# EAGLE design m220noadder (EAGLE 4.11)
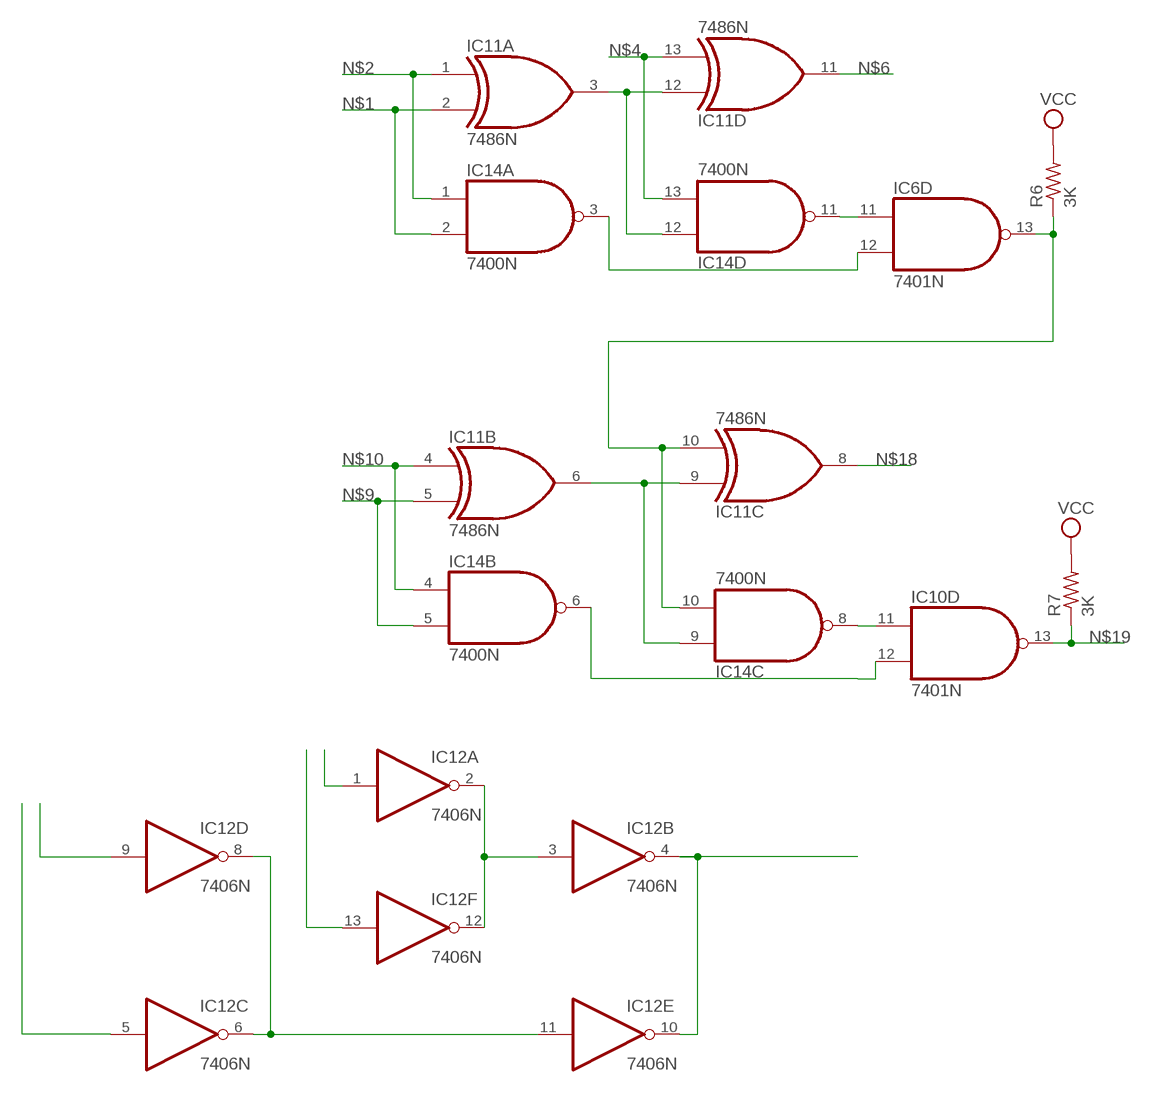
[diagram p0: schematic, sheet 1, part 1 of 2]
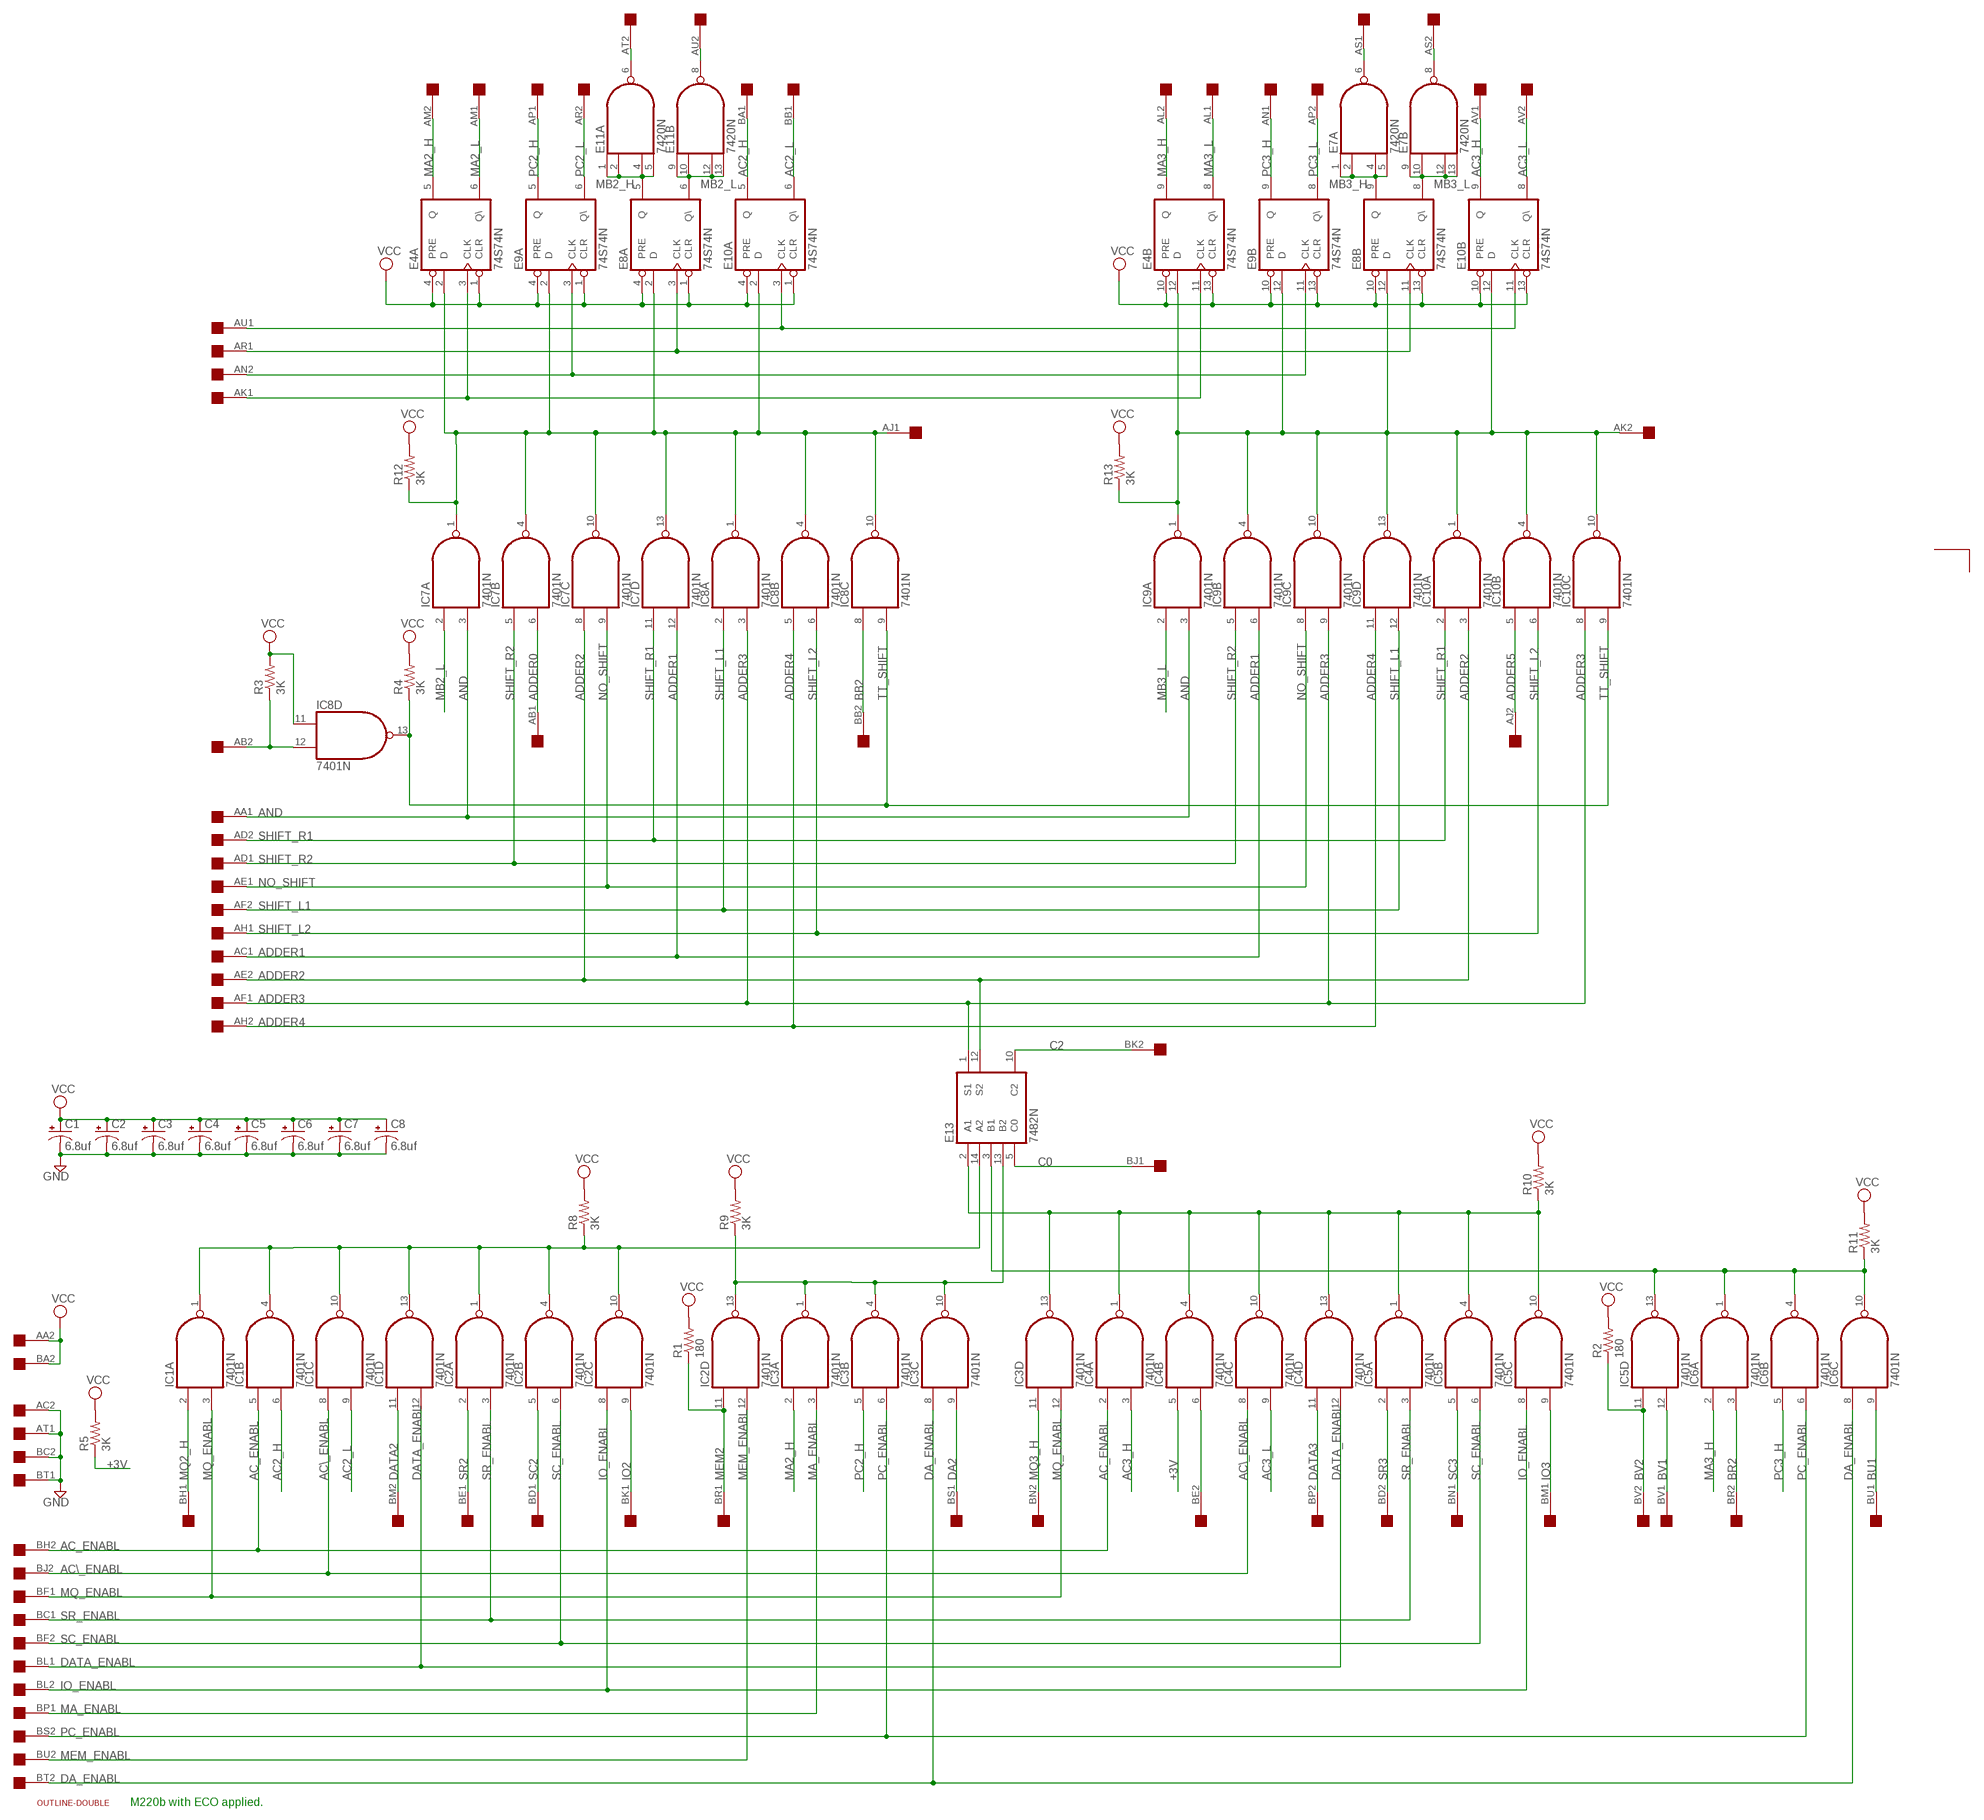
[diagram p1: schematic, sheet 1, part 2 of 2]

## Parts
C1  6.8uf  CPOL-USE15-5AXIAL  [E15-5]
C2  6.8uf  CPOL-USE15-5AXIAL  [E15-5]
C3  6.8uf  CPOL-USE15-5AXIAL  [E15-5]
C4  6.8uf  CPOL-USE15-5AXIAL  [E15-5]
C5  6.8uf  CPOL-USE15-5AXIAL  [E15-5]
C6  6.8uf  CPOL-USE15-5AXIAL  [E15-5]
C7  6.8uf  CPOL-USE15-5AXIAL  [E15-5]
C8  6.8uf  CPOL-USE15-5AXIAL  [E15-5]
E4  74S74N  [DIL14]
E7  7420N  74S20N  [DIL14]
E8  74S74N  [DIL14]
E9  74S74N  [DIL14]
E10  74S74N  [DIL14]
E11  7420N  74S20N  [DIL14]
E13  7482N  [DIL14]
IC1  7401N  [DIL14]
IC2  7401N  [DIL14]
IC3  7401N  [DIL14]
IC4  7401N  [DIL14]
IC5  7401N  [DIL14]
IC6  7401N  [DIL14]
IC7  7401N  [DIL14]
IC8  7401N  [DIL14]
IC9  7401N  [DIL14]
IC10  7401N  [DIL14]
IC11  7486N  [DIL14]
IC12  7406N  [DIL14]
IC14  7400N  [DIL14]
R1  180  R-US_0207/10  [0207/10]
R2  180  R-US_0207/10  [0207/10]
R3  3K  R-US_0207/10  [0207/10]
R4  3K  R-US_0207/10  [0207/10]
R5  3K  R-US_0207/10  [0207/10]
R6  3K  R-US_0207/10  [0207/10]
R7  3K  R-US_0207/10  [0207/10]
R8  3K  R-US_0207/10  [0207/10]
R9  3K  R-US_0207/10  [0207/10]
R10  3K  R-US_0207/10  [0207/10]
R11  3K  R-US_0207/10  [0207/10]
R12  3K  R-US_0207/10  [0207/10]
R13  3K  R-US_0207/10  [0207/10]
U$1  DOUBLE  [EDGE-CON4]
U$2  OUTLINE-DOUBLE  [DOUBLE]

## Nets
+3V: IC4.5(B:I0) R5.1
AC2_H: E10.5(A:Q) IC1.6(B:I1) U$1.BA1
AC2_L: E10.6(A:Q\) IC1.9(C:I1) U$1.BB1
AC3_H: E10.9(B:Q) IC4.3(A:I1) U$1.AV1
AC3_L: E10.8(B:Q\) IC4.9(C:I1) U$1.AV2
AC\_ENABL: IC1.8(C:I0) IC4.8(C:I0) U$1.BJ2
AC_ENABL: IC1.5(B:I0) IC4.2(A:I0) U$1.BH2
ADDER0: IC7.6(B:I1) U$1.AB1
ADDER1: IC7.12(D:I1) IC9.6(B:I1) U$1.AC1
ADDER2: E13.12(S2) IC7.8(C:I0) IC10.3(A:I1) U$1.AE2
ADDER3: E13.1(S1) IC8.3(A:I1) IC9.9(C:I1) IC10.8(C:I0) U$1.AF1
ADDER4: IC8.5(B:I0) IC9.11(D:I0) U$1.AH2
ADDER5: IC10.5(B:I0) U$1.AJ2
AJ1: E4.2(A:D) E8.2(A:D) E9.2(A:D) E10.2(A:D) IC7.1(A:O) IC7.4(B:O) IC7.10(C:O) IC7.13(D:O) IC8.1(A:O) IC8.4(B:O) IC8.10(C:O) R12.1 U$1.AJ1
AK1: E4.3(A:CLK) E4.11(B:CLK) U$1.AK1
AK2: E4.12(B:D) E8.12(B:D) E9.12(B:D) E10.12(B:D) IC9.1(A:O) IC9.4(B:O) IC9.10(C:O) IC9.13(D:O) IC10.1(A:O) IC10.4(B:O) IC10.10(C:O) R13.1 U$1.AK2
AN2: E9.3(A:CLK) E9.11(B:CLK) U$1.AN2
AND: IC7.3(A:I1) IC9.3(A:I1) U$1.AA1
AR1: E8.3(A:CLK) E8.11(B:CLK) U$1.AR1
AS1: E7.6(A:O) U$1.AS1
AS2: E7.8(B:O) U$1.AS2
AT2: E11.6(A:O) U$1.AT2
AU1: E10.3(A:CLK) E10.11(B:CLK) U$1.AU1
AU2: E11.8(B:O) U$1.AU2
BB2: IC8.8(C:I0) U$1.BB2
BE2: IC4.6(B:I1) U$1.BE2
BR2: IC6.3(A:I1) U$1.BR2
BU1: IC6.9(C:I1) U$1.BU1
BV1: IC5.12(D:I1) U$1.BV1
BV2: IC5.11(D:I0) R2.1 U$1.BV2
C0: E13.5(C0) U$1.BJ1
C2: E13.10(C2) U$1.BK2
DA2: IC3.9(C:I1) U$1.BS1
DA_ENABL: IC3.8(C:I0) IC6.8(C:I0) U$1.BT2
DATA2: IC1.11(D:I0) U$1.BM2
DATA3: IC4.11(D:I0) U$1.BP2
DATA_ENABL: IC1.12(D:I1) IC4.12(D:I1) U$1.BL1
GND: C1.- C2.- C3.- C4.- C5.- C6.- C7.- C8.- U$1.AC2 U$1.AT1 U$1.BC2 U$1.BT1
IO2: IC2.9(C:I1) U$1.BK1
IO3: IC5.9(C:I1) U$1.BM1
IO_ENABL: IC2.8(C:I0) IC5.8(C:I0) U$1.BL2
MA2_H: E4.5(A:Q) IC3.2(A:I0) U$1.AM2
MA2_L: E4.6(A:Q\) U$1.AM1
MA3_H: E4.9(B:Q) IC6.2(A:I0) U$1.AL2
MA3_L: E4.8(B:Q\) U$1.AL1
MA_ENABL: IC3.3(A:I1) U$1.BP1
MB2_H: E8.5(A:Q) E11.1(A:I0) E11.2(A:I1) E11.4(A:I2) E11.5(A:I3)
MB2_L: E8.6(A:Q\) E11.9(B:I0) E11.10(B:I1) E11.12(B:I2) E11.13(B:I3) IC7.2(A:I0)
MB3_H: E7.1(A:I0) E7.2(A:I1) E7.4(A:I2) E7.5(A:I3) E8.9(B:Q)
MB3_L: E7.9(B:I0) E7.10(B:I1) E7.12(B:I2) E7.13(B:I3) E8.8(B:Q\) IC9.2(A:I0)
MEM2: IC2.11(D:I0) R1.1 U$1.BR1
MEM_ENABL: IC2.12(D:I1) U$1.BU2
MQ2_H: IC1.2(A:I0) U$1.BH1
MQ3_H: IC3.11(D:I0) U$1.BN2
MQ_ENABL: IC1.3(A:I1) IC3.12(D:I1) U$1.BF1
N$1: IC11.2(A:I1) IC14.2(A:I1)
N$2: IC11.1(A:I0) IC14.1(A:I0)
N$3: IC11.3(A:O) IC11.12(D:I0) IC14.12(D:I0)
N$4: IC11.13(D:I1) IC14.13(D:I1)
N$5: E13.14(A2) IC1.1(A:O) IC1.4(B:O) IC1.10(C:O) IC1.13(D:O) IC2.1(A:O) IC2.4(B:O) IC2.10(C:O) R8.1
N$6: IC11.11(D:O)
N$7: IC6.12(D:I1) IC14.3(A:O)
N$8: E13.2(A1) IC3.13(D:O) IC4.1(A:O) IC4.4(B:O) IC4.10(C:O) IC4.13(D:O) IC5.1(A:O) IC5.4(B:O) IC5.10(C:O) R10.1
N$9: IC11.5(B:I1) IC14.5(B:I1)
N$10: IC11.4(B:I0) IC14.4(B:I0)
N$11: IC11.6(B:O) IC11.9(C:I0) IC14.9(C:I0)
N$12: E13.13(B2) IC2.13(D:O) IC3.1(A:O) IC3.4(B:O) IC3.10(C:O) R9.1
N$13: IC6.13(D:O) IC11.10(C:I1) IC14.10(C:I1) R6.1
N$14: E13.3(B1) IC5.13(D:O) IC6.1(A:O) IC6.4(B:O) IC6.10(C:O) R11.1
N$15: IC10.12(D:I1) IC14.6(B:O)
N$16: IC6.11(D:I0) IC14.11(D:O)
N$17: IC10.11(D:I0) IC14.8(C:O)
N$18: IC11.8(C:O)
N$19: IC10.13(D:O) R7.1
N$20: IC12.5(C:I)
N$21: IC12.9(D:I)
N$22: IC12.6(C:O) IC12.8(D:O) IC12.11(E:I)
N$23: IC12.13(F:I)
N$24: IC12.1(A:I)
N$25: IC12.2(A:O) IC12.3(B:I) IC12.12(F:O)
N$26: IC12.4(B:O) IC12.10(E:O)
NO_SHIFT: IC7.9(C:I1) IC9.8(C:I0) U$1.AE1
PC2_H: E9.5(A:Q) IC3.5(B:I0) U$1.AP1
PC2_L: E9.6(A:Q\) U$1.AR2
PC3_H: E9.9(B:Q) IC6.5(B:I0) U$1.AN1
PC3_L: E9.8(B:Q\) U$1.AP2
PC_ENABL: IC3.6(B:I1) IC6.6(B:I1) U$1.BS2
SC2: IC2.5(B:I0) U$1.BD1
SC3: IC5.5(B:I0) U$1.BN1
SC_ENABL: IC2.6(B:I1) IC5.6(B:I1) U$1.BF2
SHIFT_L1: IC8.2(A:I0) IC9.12(D:I1) U$1.AF2
SHIFT_L2: IC8.6(B:I1) IC10.6(B:I1) U$1.AH1
SHIFT_R1: IC7.11(D:I0) IC10.2(A:I0) U$1.AD2
SHIFT_R2: IC7.5(B:I0) IC9.5(B:I0) U$1.AD1
SR2: IC2.2(A:I0) U$1.BE1
SR3: IC5.2(A:I0) U$1.BD2
SR_ENABL: IC2.3(A:I1) IC5.3(A:I1) U$1.BC1
TT_SHIFT: IC8.9(C:I1) IC8.13(D:O) IC10.9(C:I1) R4.1
TT_SHIFT\: IC8.12(D:I1) R3.1 U$1.AB2
VCC: C1.+ C2.+ C3.+ C4.+ C5.+ C6.+ C7.+ C8.+ E4.1(A:CLR) E4.4(A:PRE) E4.10(B:PRE) E4.13(B:CLR) E8.1(A:CLR) E8.4(A:PRE) E8.10(B:PRE) E8.13(B:CLR) E9.1(A:CLR) E9.4(A:PRE) E9.10(B:PRE) E9.13(B:CLR) E10.1(A:CLR) E10.4(A:PRE) E10.10(B:PRE) E10.13(B:CLR) IC8.11(D:I0) R1.2 R2.2 R3.2 R4.2 R5.2 R6.2 R7.2 R8.2 R9.2 R10.2 R11.2 R12.2 R13.2 U$1.AA2 U$1.BA2

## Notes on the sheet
- M220b with ECO applied.

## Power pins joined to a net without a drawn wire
GND: E4.7(P:GND) E7.7(P:GND) E8.7(P:GND) E9.7(P:GND) E10.7(P:GND) E11.7(P:GND) E13.7(GND) IC1.7(P:GND) IC2.7(P:GND) IC3.7(P:GND) IC4.7(P:GND) IC5.7(P:GND) IC6.7(P:GND) IC7.7(P:GND) IC8.7(P:GND) IC9.7(P:GND) IC10.7(P:GND) IC11.7(P:GND) IC12.7(P:GND) IC14.7(P:GND)
VCC: E4.14(P:VCC) E7.14(P:VCC) E8.14(P:VCC) E9.14(P:VCC) E10.14(P:VCC) E11.14(P:VCC) E13.4(VCC) IC1.14(P:VCC) IC2.14(P:VCC) IC3.14(P:VCC) IC4.14(P:VCC) IC5.14(P:VCC) IC6.14(P:VCC) IC7.14(P:VCC) IC8.14(P:VCC) IC9.14(P:VCC) IC10.14(P:VCC) IC11.14(P:VCC) IC12.14(P:VCC) IC14.14(P:VCC)

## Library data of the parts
C1-C8 = rcl:CPOL-US: POLARIZED CAPACITOR, American symbol
E4 E8-E10 = 74xx-us:74*74: Dual D type positive edge triggered FLIP FLOP, preset and clear
E7 E11 = 74xx-jameco:74*20: Dual 4-input NAND gate
E13 = 74xx-eu:74*82: 2-bit binary full ADDER
IC1-IC10 = 74xx-jameco:74*01: Quad 2-input NAND gate, open collector
IC11 = 74xx-jameco:74*86: Quad 2-input EXCLUSIV-OR (XOR) gate
IC12 = 74xx-jameco:74*06: Hex INVERTER, open collector high-voltage output
IC14 = 74xx-jameco:74*00: Quad 2-input NAND gate
R1-R13 = rcl:R-US_: RESISTOR, American symbol
U$1 = dec-con:DOUBLE: Double-Height DEC board
U$2 = dec-con:OUTLINE-*: Board outlines for DEC boards.

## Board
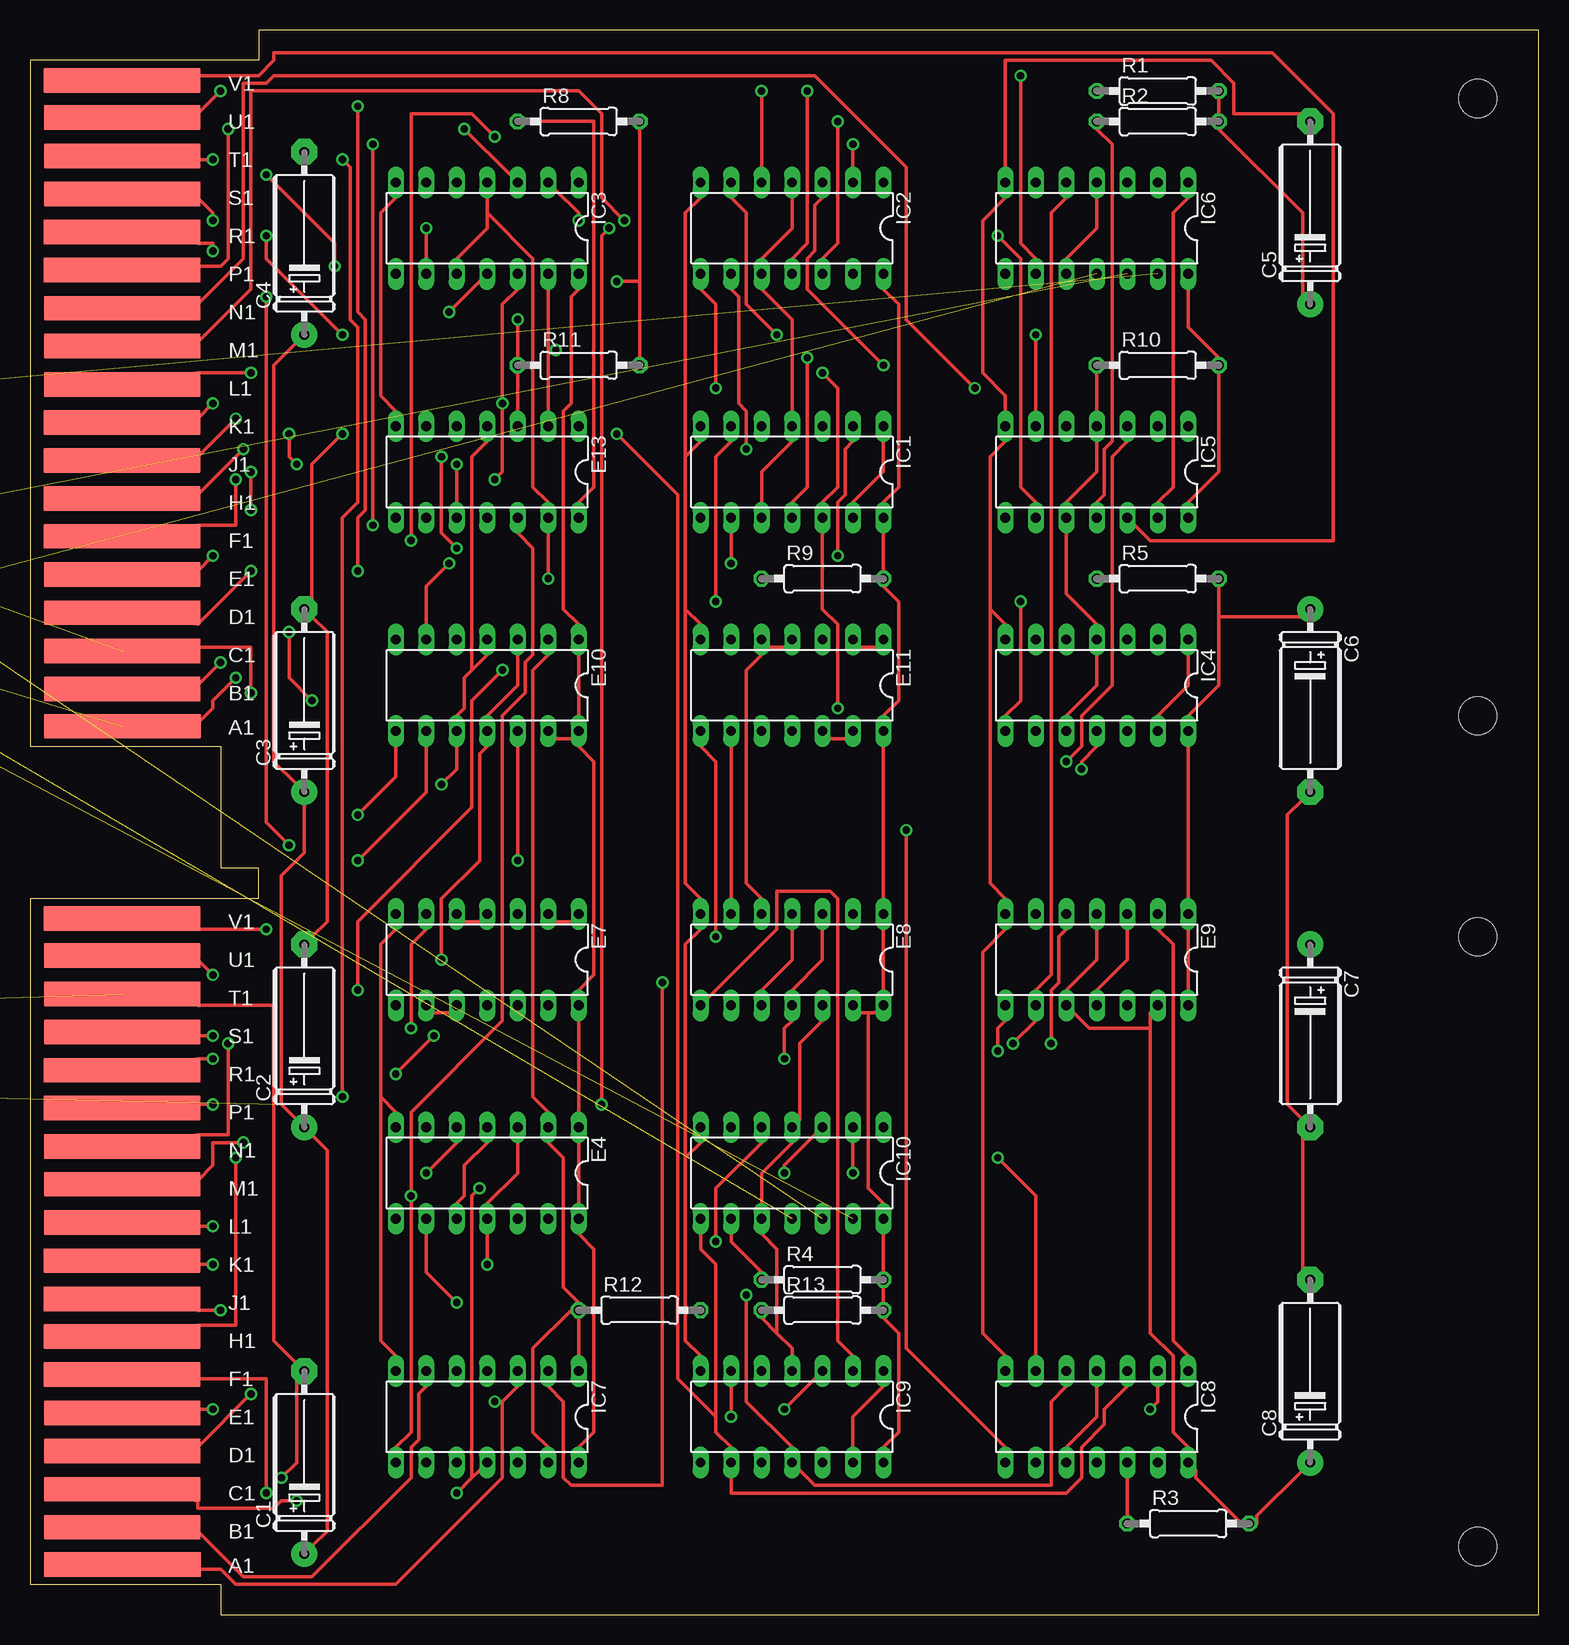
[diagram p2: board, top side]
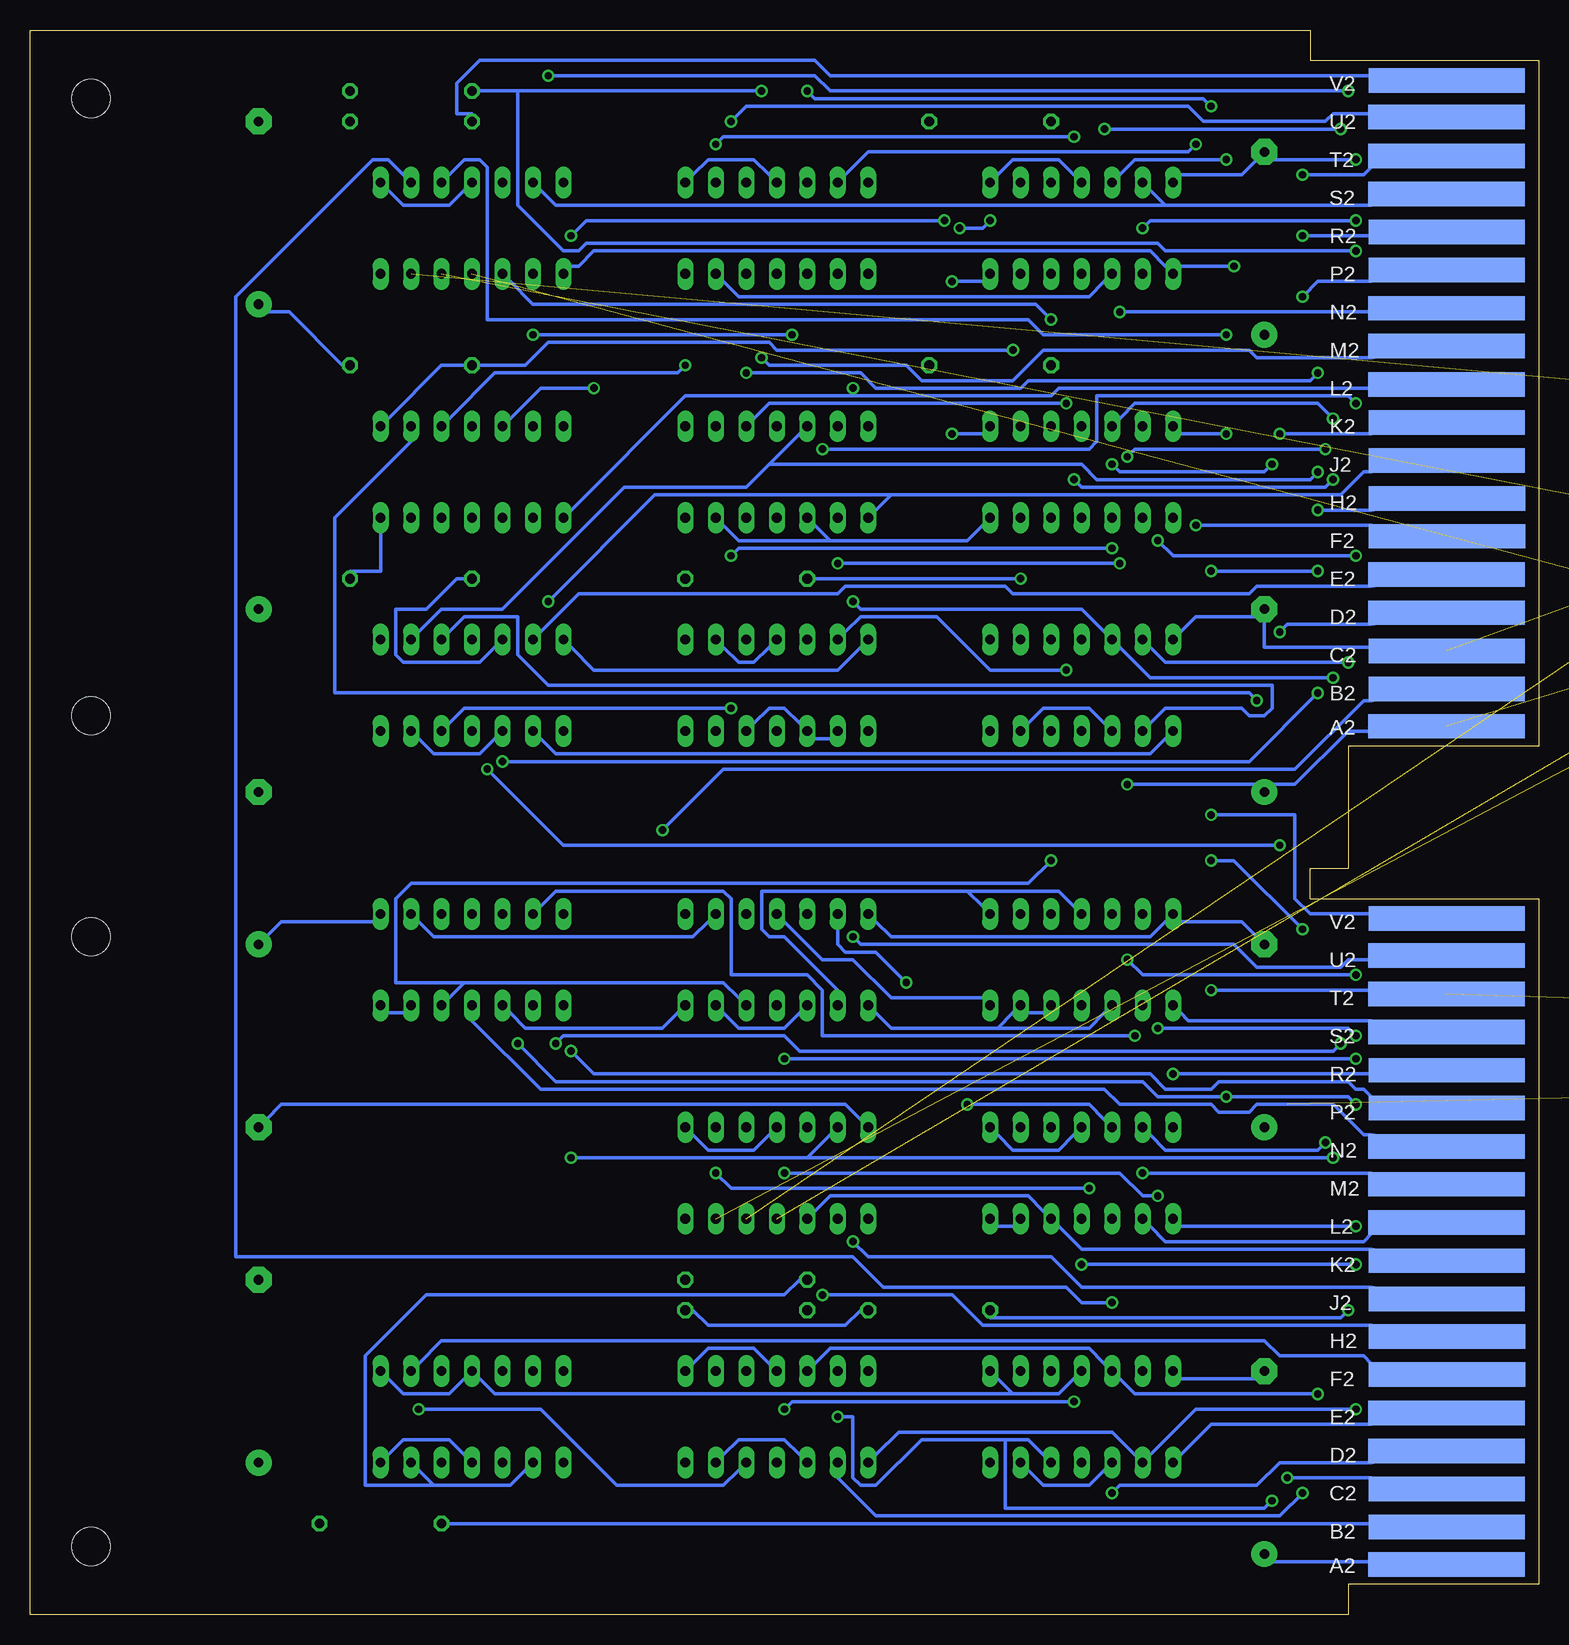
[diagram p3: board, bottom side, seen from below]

Size 125.73 x 132.08 mm. Coordinates in mm from the lower left corner, seen from the top.
Copper layers (1*16): Top 0.035mm / dielectric 1.5mm / Bottom 0.035mm
Design rules "olimex10mil": minimum track width 12mil, minimum drill 24mil, track to track 12mil, track to pad 12mil, pad to pad 12mil, via to via 12mil, smd to smd 10mil, copper to edge 25mil, drill to drill 10mil, minimum pad ring 10mil, minimum via ring 8mil, stop-mask expansion 0mil, vias tented up to drill 0mil, thermal gap 10mil

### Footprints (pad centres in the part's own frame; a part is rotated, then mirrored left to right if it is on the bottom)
E15-5 = drill 0.813 pad 2.159 round: + -7.62,0 | drill 0.813 pad 2.159 octagon: - 7.62,0
DIL14 = drill 0.813 long: 1 -7.62,-3.81; 2 -5.08,-3.81; 3 -2.54,-3.81; 4 0,-3.81; 5 2.54,-3.81; 6 5.08,-3.81; 7 7.62,-3.81; 8 7.62,3.81; 9 5.08,3.81; 10 2.54,3.81; 11 0,3.81; 12 -2.54,3.81; 13 -5.08,3.81; 14 -7.62,3.81
0207/10 = drill 0.813 octagon: 1 -5.08,0; 2 5.08,0
EDGE-CON4 = smd 13.017 x 2.032: AA1 7.709,4.207; AB1 7.684,7.312; AC1 7.684,10.474; AD1 7.684,13.665; AE1 7.693,16.84; AF1 7.668,20.041; AH1 7.668,23.19; AJ1 7.668,26.34; AK1 7.668,29.515; AL1 7.693,32.69; AM1 7.693,35.89; AN1 7.693,39.04; AP1 7.668,42.24; AR1 7.668,45.39; AS1 7.693,48.565; AT1 7.693,51.74; AU1 7.693,54.94; AV1 7.668,58.026; BA1 7.709,74.057; BB1 7.684,77.162; BC1 7.684,80.324; BD1 7.684,83.515; BE1 7.693,86.69; BF1 7.668,89.891; BH1 7.668,93.04; BJ1 7.668,96.19; BK1 7.668,99.365; BL1 7.693,102.54; BM1 7.693,105.74; BN1 7.693,108.89; BP1 7.668,112.09; BR1 7.668,115.24; BS1 7.693,118.415; BT1 7.693,121.59; BU1 7.693,124.79; BV1 7.668,127.876 | smd 13.017 x 2.032 bottom: AA2 7.69,4.207; AB2 7.668,7.328; AC2 7.668,10.49; AD2 7.693,13.665; AE2 7.693,16.84; AF2 7.642,20.041; AH2 7.642,23.19; AJ2 7.668,26.34; AK2 7.668,29.515; AL2 7.693,32.69; AM2 7.693,35.89; AN2 7.693,39.04; AP2 7.668,42.24; AR2 7.668,45.39; AS2 7.693,48.565; AT2 7.693,51.74; AU2 7.693,54.966; AV2 7.668,58.026; BA2 7.69,74.057; BB2 7.668,77.178; BC2 7.668,80.34; BD2 7.693,83.515; BE2 7.693,86.69; BF2 7.642,89.891; BH2 7.642,93.04; BJ2 7.668,96.19; BK2 7.668,99.365; BL2 7.693,102.54; BM2 7.693,105.74; BN2 7.693,108.89; BP2 7.668,112.09; BR2 7.668,115.24; BS2 7.693,118.415; BT2 7.693,121.59; BU2 7.693,124.816; BV2 7.668,127.876
DOUBLE = hole 3.175: 120.65,56.515; 120.65,5.715; 120.65,74.93; 120.65,126.365

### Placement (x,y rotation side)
C1  22.86,12.7 90 top
C2  22.86,48.26 90 top
C3  22.86,76.2 90 top
C4  22.86,114.3 90 top
C5  106.68,116.84 90 top
C6  106.68,76.2 270 top
C7  106.68,48.26 270 top
C8  106.68,20.32 90 top
E4  38.1,36.83 180 top
E7  38.1,54.61 180 top
E8  63.5,54.61 180 top
E9  88.9,54.61 180 top
E10  38.1,77.47 180 top
E11  63.5,77.47 180 top
E13  38.1,95.25 180 top
IC1  63.5,95.25 180 top
IC2  63.5,115.57 180 top
IC3  38.1,115.57 180 top
IC4  88.9,77.47 180 top
IC5  88.9,95.25 180 top
IC6  88.9,115.57 180 top
IC7  38.1,16.51 180 top
IC8  88.9,16.51 180 top
IC9  63.5,16.51 180 top
IC10  63.5,36.83 180 top
IC11  not placed on the board
IC12  not placed on the board
IC14  not placed on the board
R1  93.98,127 0 top
R2  93.98,124.46 0 top
R3  96.52,7.62 0 top
R4  66.04,27.94 0 top
R5  93.98,86.36 0 top
R6  not placed on the board
R7  not placed on the board
R8  45.72,124.46 0 top
R9  66.04,86.36 0 top
R10  93.98,104.14 0 top
R11  45.72,104.14 0 top
R12  50.8,25.4 0 top
R13  66.04,25.4 0 top
U$1  0,0 0 top
U$2  0,0 0 top

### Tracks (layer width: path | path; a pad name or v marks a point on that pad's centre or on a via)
+3V
  Bottom 0.305: IC4.5 87,80.64 88.27,79.38 94.62,79.38 95.25,80.01 95.25,83.82 92.71,83.82 90.17,86.36 89.54,86.36 R5.1
AC2_H  (via drill 0.61)
  Top 0.305: v17.15,78.11 15.24,76.2 15.24,75.56 13.97,74.3 U$1.BA1 | v57.15,84.45 57.15,96.52 58.42,97.79 IC1.6
  Bottom 0.305: v17.15,78.11 32.39,78.11 34.93,80.64 E10.5 36.2,81.92 38.1,83.82 56.52,83.82 v57.15,84.45
AC2_L  (via drill 0.61)
  Top 0.305: v15.88,79.38 13.97,77.47 U$1.BB1 | v58.42,87.63 58.42,90.17 IC1.9 | v34.93,87.63 33.02,85.72 33.02,82.55 E10.6
  Bottom 0.305: v15.88,79.38 31.12,79.38 32.39,80.64 E10.6 | v34.93,87.63 v58.42,87.63
AC3_H  (via drill 0.61)
  Top 0.305: v19.69,57.15 13.97,57.15 U$1.AV1 | v27.31,62.87 33.02,68.58 33.02,72.39 E10.9
  Bottom 0.305: E10.9 32.39,74.3 31.12,75.56 24.77,75.56 24.13,74.93 22.86,74.93 22.23,75.56 22.23,77.47 82.55,77.47 85.09,80.01 85.09,83.19 89.54,83.19 90.81,81.92 IC4.3 | v19.69,57.15 25.4,62.87 v27.31,62.87
AC3_L  (via drill 0.61)
  Top 0.305: v27.31,66.67 30.48,69.85 30.48,72.39 E10.8
  Bottom 0.305: E10.8 31.12,73.03 32.39,71.75 81.92,71.75 83.19,73.03 IC4.9 | v27.31,66.67 20.32,66.67 20.32,59.69 19.05,58.42 13.97,58.42 U$1.AV2
AC\_ENABL  (via drill 0.61)
  Top 0.305: v82.55,84.45 82.55,76.2 81.28,74.93 IC4.8
  Bottom 0.305: 53.98,93.34 55.25,92.08 IC1.8 | 53.98,93.34 16.51,93.34 14.61,95.25 13.97,95.25 U$1.BJ2 | v82.55,84.45 73.66,93.34 53.98,93.34
AC_ENABL  (via drill 0.61)
  Top 0.305: v18.42,92.08 v18.42,95.25
  Bottom 0.305: 64.14,95.89 66.04,93.98 76.2,93.98 86.36,83.82 91.44,83.82 93.35,81.92 IC4.2 | 64.14,95.89 61.6,98.42 IC1.5 | v18.42,92.08 13.97,92.08 U$1.BH2 | v18.42,95.25 19.05,94.61 36.83,94.61 38.1,95.89 64.14,95.89
ADDER0
  Top 0.305: IC7.6 33.02,19.05 32.39,18.41 32.39,14.61 31.75,13.97 31.75,11.43 23.5,3.17 17.78,3.17 13.97,6.99 U$1.AB1
ADDER1  (via drill 0.61)
  Top 0.305: v58.42,16.51 58.42,19.05 IC9.6 | v22.23,9.53 20.96,9.53 20.32,8.89 13.97,8.89 13.97,9.53 U$1.AC1
  Bottom 0.305: 44.45,14.61 51.44,14.61 55.25,10.79 56.52,10.79 57.15,11.43 57.15,16.51 v58.42,16.51 | 44.45,14.61 42.55,14.61 41.28,13.34 IC7.12 | 44.45,14.61 44.45,8.89 22.86,8.89 v22.23,9.53
ADDER2  (via drill 0.61)
  Top 0.305: v62.87,36.83 62.87,37.47 65.41,40.01 IC10.3 | IC7.8 30.48,13.97 31.75,15.24 v31.75,34.92 31.75,41.91 39.37,49.53 39.37,74.93 41.28,76.83 41.28,79.38 41.91,80.01 41.91,88.9 40.64,90.17 E13.12
  Bottom 0.305: IC7.8 29.85,13.34 27.31,15.88 13.97,15.88 U$1.AE2 | v62.87,36.83 34.93,36.83 33.02,34.92 v31.75,34.92
ADDER3  (via drill 0.61)
  Top 0.305: 57.15,16.51 57.15,29.21 55.88,30.48 55.88,31.75 IC10.8 | 57.15,16.51 57.15,15.24 58.42,13.97 IC9.9 58.42,11.43 58.42,10.16 86.36,10.16 87.63,11.43 87.63,13.97 89.54,15.88 89.54,17.14 91.44,19.05 IC8.3 | v48.9,98.42 53.98,93.34 53.98,19.68 57.15,16.51 | v19.69,10.16 19.69,19.68 13.97,19.68 U$1.AF1
  Bottom 0.305: v48.9,98.42 46.36,98.42 E13.1 | v19.69,10.16 21.59,8.26 55.25,8.26 58.42,11.43 IC9.9
ADDER4  (via drill 0.61)
  Top 0.305: IC8.5 86.36,19.05 85.09,17.78 85.09,10.79 65.41,10.79 64.14,12.06 IC9.11 63.5,13.97 59.69,17.78 v59.69,26.67
  Bottom 0.305: v59.69,26.67 48.9,26.67 46.36,24.13 13.97,24.13 U$1.AH2
ADDER5  (via drill 0.61)
  Top 0.305: v57.15,31.11 57.15,35.56 60.96,39.37 IC10.5
  Bottom 0.305: v57.15,31.11 55.88,29.84 40.64,29.84 38.1,27.3 13.97,27.3 U$1.AJ2
AJ1  (via drill 0.61)
  Top 0.305: IC8.10 86.36,13.97 88.9,16.51 88.9,19.05 IC8.4 | IC8.1 96.52,21.59 95.25,22.86 95.25,55.88 93.98,57.15 E9.2 | R12.1 45.72,24.77 45.72,21.59 IC7.1 | R12.1 45.72,26.04 44.45,27.3 44.45,38.1 43.18,39.37 E4.2 43.18,41.91 41.91,43.18 41.91,78.74 43.18,80.01 E10.2 | IC7.13 43.18,13.97 41.91,15.24 41.91,22.23 45.09,25.4 R12.1 | v15.88,25.4 13.97,25.4 U$1.AJ1
  Bottom 0.305: IC8.1 95.89,19.68 94.62,18.41 90.81,18.41 89.54,19.68 IC8.4 88.27,19.68 87,18.41 43.82,18.41 | E8.2 69.22,57.78 70.49,56.52 92.08,56.52 93.35,57.78 E9.2 | IC7.10 36.2,12.06 37.47,10.79 41.28,10.79 42.55,12.06 IC7.13 | 43.82,18.41 40.01,18.41 38.74,19.68 IC7.4 | 43.82,18.41 45.09,19.68 IC7.1 | v15.88,25.4 16.51,24.77 45.72,24.77 R12.1
AK1  (via drill 0.61)
  Top 0.305: E4.3 40.64,39.37 40.64,36.83 38.1,34.29 E4.11 38.1,31.75 v38.1,29.21 | v15.24,29.21 13.97,29.21 U$1.AK1
  Bottom 0.305: v15.24,29.21 v38.1,29.21
AK2  (via drill 0.61)
  Top 0.305: IC9.1 71.12,19.05 68.58,16.51 68.58,13.97 IC9.13 | 62.23,23.5 63.5,22.23 63.5,21.59 IC9.4 | 62.23,23.5 60.96,24.77 R13.1 | 62.23,23.5 62.23,30.48 60.96,31.75 IC10.10 60.96,34.29 60.96,36.83 63.5,39.37 IC10.4 64.14,41.27 64.14,47.62 66.04,49.53 E8.12 | v40.64,62.87 40.64,72.39 E10.12
  Bottom 0.305: U$1.AK2 13.97,30.48 38.1,30.48 40.01,32.38 E4.12 41.28,33.66 42.55,34.92 59.06,34.92 60.33,33.66 IC10.10 | IC9.10 61.6,13.34 62.87,14.61 66.68,14.61 67.95,13.34 IC9.13 | IC10.1 70.49,40.01 69.22,38.73 65.41,38.73 64.14,40.01 IC10.4 | 89.54,52.7 90.81,51.44 E9.12 | 89.54,52.7 67.95,52.7 66.68,51.44 E8.12 | v40.64,62.87 42.55,60.96 93.98,60.96 95.25,59.69 95.25,52.7 89.54,52.7 | IC9.1 70.49,20.95 69.22,22.23 65.41,22.23 64.14,20.95 IC9.4
AN2
  Top 0.305: E9.11 88.9,52.07 91.44,54.61 91.44,57.15 E9.3
  Bottom 0.305: E9.11 88.9,49.53 83.19,43.81 36.2,43.81 34.93,42.55 27.31,42.55 26.67,41.91 24.13,41.91 23.5,42.55 17.15,42.55 14.61,40.01 13.97,40.01 U$1.AN2
AND  (via drill 0.61)
  Top 0.305: 39.37,17.78 40.64,19.05 IC7.3 | 39.37,17.78 39.37,11.43 30.48,2.54 17.15,2.54 15.88,3.81 13.97,3.81 U$1.AA1 | v62.87,17.14 65.41,19.68 IC9.3 | 39.37,17.78 v38.74,17.78
  Bottom 0.305: v62.87,17.14 62.23,17.78 v38.74,17.78
AR1  (via drill 0.61)
  Top 0.305: E8.3 66.04,57.15 66.04,54.61 63.5,52.07 E8.11 63.5,49.53 62.87,48.9 v62.87,46.35 | v15.24,46.35 13.97,46.35 U$1.AR1
  Bottom 0.305: v15.24,46.35 v62.87,46.35
AS1  (via drill 0.61)
  Top 0.305: v31.75,48.9 31.75,55.88 33.02,57.15 E7.6 | v15.24,48.26 13.97,48.26 U$1.AS1
  Bottom 0.305: v31.75,48.9 15.88,48.9 v15.24,48.26
AS2
  Bottom 0.305: E7.8 29.85,50.16 29.21,49.53 13.97,49.53 U$1.AS2
AT2  (via drill 0.61)
  Top 0.305: v39.37,78.74 36.83,76.2 36.83,67.31 27.31,57.78 v27.31,52.07
  Bottom 0.305: v39.37,78.74 45.72,78.74 50.17,83.19 56.52,83.19 57.79,81.92 E11.6 | v27.31,52.07 13.97,52.07 U$1.AT2
AU1  (via drill 0.61)
  Top 0.305: E10.3 40.64,80.01 40.64,77.47 38.1,74.93 E10.11 38.1,72.39 37.47,71.75 37.47,62.87 34.29,59.69 v34.29,54.61 | v15.24,53.34 13.97,54.61 U$1.AU1
  Bottom 0.305: v34.29,54.61 33.02,53.34 v15.24,53.34
AU2  (via drill 0.61)
  Top 0.305: v57.15,56.52 57.15,71.12 55.88,72.39 E11.8
  Bottom 0.305: v57.15,56.52 56.52,55.88 25.4,55.88 23.5,53.98 16.51,53.98 15.88,54.61 13.97,54.61 U$1.AU2
BB2  (via drill 0.61)
  Top 0.305: v73.03,65.41 73.03,22.23 81.28,13.97 IC8.8
  Bottom 0.305: v73.03,65.41 67.95,70.48 20.32,70.48 14.61,76.2 13.97,76.2 U$1.BB2
BE2
  Bottom 0.305: IC4.6 83.19,81.92 80.01,85.09 58.42,85.09 57.79,85.72 44.45,85.72 43.82,85.09 24.13,85.09 23.5,85.72 13.97,85.72 U$1.BE2
BR2  (via drill 0.61)
  Top 0.305: v26.04,106.68 19.69,113.03 v19.69,114.94
  Bottom 0.305: v26.04,106.68 41.28,106.68 42.55,107.95 87.63,107.95 87.63,120.65 88.27,121.28 89.54,121.28 90.81,120.02 IC6.3 | v19.69,114.94 13.97,114.94 U$1.BR2
BU1  (via drill 0.61)
  Top 0.305: v82.55,128.27 82.55,114.3 83.82,113.03 IC6.9 | v15.88,127 13.97,125.09 U$1.BU1
  Bottom 0.305: v82.55,128.27 60.33,128.27 59.06,127 v15.88,127
BV1
  Top 0.305: IC5.12 92.08,90.81 93.35,89.53 108.59,89.53 108.59,125.09 103.51,130.18 20.32,130.18 20.32,129.54 19.05,128.27 13.97,128.27 U$1.BV1
BV2
  Top 0.305: IC5.11 88.9,92.71 89.54,93.34 89.54,97.16 90.17,97.79 90.17,122.56 88.9,123.83 R2.1
  Bottom 0.305: U$1.BV2 13.97,128.27 59.06,128.27 60.33,129.54 88.27,129.54 90.17,127.64 90.17,125.09 88.9,125.09 R2.1
C0  (via drill 0.61)
  Top 0.305: v17.15,99.69 13.97,96.52 U$1.BJ1
  Bottom 0.305: v17.15,99.69 18.42,100.97 33.66,100.97 34.93,99.69 E13.5
C2  (via drill 0.61)
  Top 0.305: v35.56,95.89 35.56,92.71 E13.10 | v22.23,95.89 21.59,96.52 v21.59,98.42
  Bottom 0.305: v35.56,95.89 34.93,95.25 22.86,95.25 v22.23,95.89 | v21.59,98.42 13.97,98.42 U$1.BK2
DA2  (via drill 0.61)
  Top 0.305: v33.02,115.57 33.02,113.03 IC3.9 | v15.24,116.2 15.24,116.84 13.97,118.11 U$1.BS1
  Bottom 0.305: v33.02,115.57 32.39,116.2 v15.24,116.2
DA_ENABL  (via drill 0.61)
  Top 0.305: v19.69,120.02 25.4,114.3 v25.4,112.39
  Bottom 0.305: IC6.8 80.65,112.39 80.01,112.39 78.74,113.67 32.39,113.67 31.12,112.39 IC3.8 29.85,112.39 v25.4,112.39 | v19.69,120.02 14.61,120.02 13.97,120.65 U$1.BT2
DATA2  (via drill 0.61)
  Top 0.305: v64.77,104.78 64.77,93.98 63.5,92.71 IC1.11
  Bottom 0.305: v64.77,104.78 64.14,104.14 52.71,104.14 51.44,102.87 43.82,102.87 41.28,105.41 24.13,105.41 23.5,104.78 13.97,104.78 U$1.BM2
DATA3  (via drill 0.61)
  Top 0.305: v87.63,70.48 87.63,71.12 88.9,72.39 IC4.11 | v21.59,64.14 19.69,66.04 v19.69,109.86
  Bottom 0.305: v87.63,70.48 81.28,64.14 v21.59,64.14 | v19.69,109.86 18.42,111.12 13.97,111.12 U$1.BP2
DATA_ENABL  (via drill 0.61)
  Top 0.305: v67.31,75.56 67.31,82.55 66.04,83.82 66.04,90.17 IC1.12 66.04,92.71 67.31,93.98 67.31,102.23 v66.04,103.5 | v18.42,103.5 13.97,103.5 U$1.BL1
  Bottom 0.305: v67.31,75.56 89.54,75.56 90.81,74.3 IC4.12 | v18.42,103.5 19.05,102.87 42.55,102.87 43.18,102.23 55.25,102.23 56.52,103.5 v66.04,103.5
GND  (via drill 0.61)  (3 unrouted)
  Top 0.305: E13.7 30.48,100.33 29.21,101.6 29.21,116.84 30.48,118.11 IC3.7 | v15.24,121.28 13.97,121.28 U$1.BT1 | 29.21,43.18 30.48,41.91 E4.7 | 29.21,43.18 29.21,55.88 30.48,57.15 E7.7 | 29.21,43.18 29.21,22.86 30.48,21.59 IC7.7 | v20.96,11.43 22.23,12.7 22.23,19.68 C1.- 22.23,20.95 20.32,22.86 20.32,50.8 13.97,50.8 U$1.AT1 | C2.- 23.5,56.52 24.77,57.78 24.77,81.92 23.5,83.19 C3.- 23.5,84.45 23.5,95.89 v26.04,98.42 | IC8.7 81.28,21.59 79.38,23.5 79.38,55.24 81.28,57.15 E9.7 81.28,59.69 80.01,60.96 80.01,83.82 | 80.01,83.82 81.28,82.55 IC4.7 | 80.01,83.82 80.01,96.52 81.28,97.79 IC5.7 81.28,100.33 81.28,101.6 79.38,103.5 79.38,116.2 81.28,118.11 IC6.7 81.28,120.65 81.28,129.54 98.43,129.54 100.33,127.64 100.33,125.09 106.05,125.09 C5.- | C8.- 106.05,28.57 106.05,40.01 C7.- 106.05,41.27 104.78,42.55 104.78,66.67 106.05,67.94 C6.- | 54.61,38.1 54.61,22.86 55.88,21.59 IC9.7 | 54.61,38.1 55.88,39.37 IC10.7 | 54.61,38.1 54.61,55.88 55.88,57.15 E8.7 55.88,59.69 54.61,60.96 54.61,83.82 | 54.61,83.82 55.88,82.55 E11.7 | 54.61,83.82 54.61,96.52 | 54.61,96.52 55.88,97.79 IC1.7 | 54.61,96.52 54.61,116.84 55.88,118.11 IC2.7
  Bottom 0.305: IC3.7 29.85,120.02 24.77,120.02 23.5,121.28 C4.- 22.23,121.28 v15.24,121.28 | E10.7 29.85,81.92 28.58,83.19 23.5,83.19 C3.- 22.86,83.19 22.86,80.64 13.97,80.64 U$1.BC2 | IC7.7 29.85,19.68 23.5,19.68 C1.- | C2.- 23.5,56.52 24.77,57.78 29.85,57.78 E7.7 31.12,57.78 32.39,56.52 53.98,56.52 55.25,57.78 E8.7 | v20.96,11.43 13.97,11.43 U$1.AC2 | v26.04,98.42 29.85,98.42 E13.7 | C7.- 106.05,41.27 104.78,42.55 57.79,42.55 56.52,41.27 IC10.7 | IC4.7 80.65,80.64 78.74,78.74 58.42,78.74 56.52,80.64 E11.7
IO2  (via drill 0.61)
  Top 0.305: v59.69,97.16 59.69,100.33 59.06,100.97 59.06,109.86 58.42,110.49 IC2.9 | v15.24,100.97 13.97,99.69 U$1.BK1
  Bottom 0.305: v59.69,97.16 37.47,97.16 36.83,97.79 36.83,101.6 15.88,101.6 v15.24,100.97
IO3  (via drill 0.61)
  Top 0.305: v80.65,114.94 82.55,113.03 82.55,93.98 83.82,92.71 IC5.9 | v49.53,116.2 47.63,118.11 47.63,125.09 45.72,127 18.42,127 18.42,110.49 13.97,106.05 U$1.BM1
  Bottom 0.305: v80.65,114.94 79.38,116.2 v49.53,116.2
IO_ENABL  (via drill 0.61)
  Top 0.305: v57.15,102.23 57.15,109.22 55.88,110.49 IC2.8
  Bottom 0.305: 57.15,101.6 40.64,101.6 40.01,102.23 13.97,102.23 U$1.BL2 | 57.15,101.6 71.12,101.6 80.65,92.08 IC5.8 | 57.15,101.6 v57.15,102.23
MA2_H  (via drill 0.61)
  Top 0.305: v33.02,36.83 35.56,39.37 E4.5 | v45.72,116.2 45.72,116.84 43.82,118.75 IC3.2 | v48.26,115.57 47.63,114.94 v47.63,42.55
  Bottom 0.305: v33.02,36.83 13.97,36.83 U$1.AM2 | v45.72,116.2 46.36,115.57 v48.26,115.57 | v47.63,42.55 37.47,42.55 36.2,41.27 E4.5
MA2_L  (via drill 0.61)
  Top 0.305: v17.78,39.37 15.24,39.37 15.24,37.47 13.97,36.2 U$1.AM1
  Bottom 0.305: v17.78,39.37 18.42,38.73 31.12,38.73 32.39,40.01 E4.6
MA3_H  (via drill 0.61)
  Top 0.305: v35.56,26.04 33.02,28.57 33.02,31.75 E4.9
  Bottom 0.305: E4.9 32.39,32.38 31.12,31.11 14.61,31.11 13.97,31.75 U$1.AL2 | v35.56,26.04 38.1,26.04 39.37,27.3 54.61,27.3 57.15,29.84 108.59,29.84 108.59,109.86 97.16,121.28 95.89,121.28 94.62,120.02 IC6.2
MA3_L  (via drill 0.61)
  Top 0.305: v15.24,32.38 13.97,32.38 U$1.AL1
  Bottom 0.305: v15.24,32.38 29.85,32.38 E4.8
MA_ENABL  (via drill 0.61)
  Top 0.305: v36.2,123.83 40.01,120.02 IC3.3 | v16.51,123.83 16.51,113.03 15.88,112.39 13.97,112.39 U$1.BP1
  Bottom 0.305: v16.51,123.83 v36.2,123.83
MB2_H
  Top 0.305: E11.2 69.22,80.64 70.49,80.64 E11.1 | E8.5 60.96,59.69 59.69,60.96 59.69,78.74 60.96,80.01 E11.5 61.6,80.64 62.87,80.64 E11.4
  Bottom 0.305: E11.2 67.95,80.64 66.68,79.38 65.41,79.38 64.14,80.64 E11.4
MB2_L  (via drill 0.61)
  Top 0.305: E11.12 66.68,73.03 67.95,73.03 E11.13 | v52.71,52.7 52.71,10.79 45.09,10.79 44.45,11.43 44.45,17.78 43.18,19.05 IC7.2 | E11.9 58.42,72.39 58.42,59.69 E8.6
  Bottom 0.305: E11.9 59.06,73.03 60.33,73.03 E11.10 61.6,74.3 62.87,75.56 64.14,75.56 65.41,74.3 E11.12 | v52.71,52.7 55.25,55.24 57.79,55.24 58.42,55.88 58.42,57.15 E8.6
MB3_H
  Top 0.305: E7.5 36.2,57.78 37.47,57.78 E7.4 | E7.2 43.82,57.78 45.09,57.78 E7.1
  Bottom 0.305: 47.63,60.33 64.77,60.33 64.77,57.15 64.14,56.52 62.87,56.52 58.42,52.07 E8.9 | 47.63,60.33 46.36,59.05 E7.1 | 47.63,60.33 40.01,60.33 38.74,59.05 E7.4
MB3_L
  Top 0.305: E7.9 33.66,50.16 34.93,50.16 E7.10 | IC9.2 68.58,21.59 67.31,22.86 67.31,59.69 66.68,60.33 62.23,60.33 62.23,57.15 56.52,51.44 E8.8
  Bottom 0.305: E7.12 41.28,50.16 42.55,50.16 E7.13 43.82,50.16 45.09,48.9 | 45.09,48.9 53.98,48.9 55.25,50.16 E8.8 | 45.09,48.9 37.47,48.9 36.2,50.16 E7.10
MEM2  (via drill 0.61)
  Top 0.305: v64.77,127 64.77,114.3 63.5,113.03 IC2.11 | v15.24,113.67 15.24,114.3 13.97,114.3 U$1.BR1
  Bottom 0.305: 85.09,127 88.27,127 R1.1 | 85.09,127 v64.77,127 | v15.24,113.67 31.12,113.67 31.75,114.3 79.38,114.3 80.01,113.67 81.28,113.67 85.09,117.47 85.09,127
MEM_ENABL  (via drill 0.61)
  Top 0.305: v67.31,124.46 67.31,114.3 66.04,113.03 IC2.12
  Bottom 0.305: v67.31,124.46 66.04,125.73 29.21,125.73 27.94,124.46 17.78,124.46 17.15,125.09 13.97,125.09 U$1.BU2
MQ2_H  (via drill 0.61)
  Top 0.305: v67.31,88.27 67.31,92.71 67.95,93.34 67.95,97.16 68.58,97.79 IC1.2 | v35.56,88.9 34.29,90.17 v34.29,96.52 | v17.78,97.16 13.97,93.34 U$1.BH1
  Bottom 0.305: v67.31,88.27 66.68,88.9 v35.56,88.9 | v34.29,96.52 33.66,97.16 v17.78,97.16
MQ3_H  (via drill 0.61)
  Top 0.305: v34.93,108.58 37.47,111.12 IC3.11
  Bottom 0.305: v34.93,108.58 13.97,108.58 U$1.BN2
MQ_ENABL  (via drill 0.61)
  Top 0.305: IC3.12 40.64,110.49 39.37,109.22 v39.37,100.97 39.37,95.25 v38.74,94.61 | v17.15,94.61 17.15,90.81 13.97,90.81 U$1.BF1
  Bottom 0.305: v39.37,100.97 64.14,100.97 65.41,99.69 IC1.3 | v17.15,94.61 17.78,93.98 38.1,93.98 v38.74,94.61
N$1  (1 unrouted)
N$2  (1 unrouted)
N$3  (2 unrouted)
N$4  (1 unrouted)
N$5
  Top 0.305: IC2.4 63.5,118.11 63.5,115.57 60.96,113.03 IC2.10 60.96,110.49 63.5,107.95 63.5,100.33 IC1.4 63.5,97.79 60.96,95.25 60.96,92.71 IC1.10 | IC1.13 68.58,92.71 71.12,95.25 71.12,97.79 IC1.1 | R8.1 41.28,124.46 46.99,124.46 46.99,93.98 45.72,92.71 E13.14
  Bottom 0.305: IC2.1 70.49,120.02 69.22,121.28 65.41,121.28 64.14,120.02 IC2.4 | 59.06,89.53 47.63,89.53 46.36,90.81 E13.14 | 59.06,89.53 60.33,90.81 IC1.10 | 59.06,89.53 66.68,89.53 67.95,90.81 IC1.13
N$7  (1 unrouted)
N$8  (via drill 0.61)
  Top 0.305: 43.18,105.41 43.18,110.49 IC3.13 | 43.18,105.41 43.18,100.33 E13.2 | IC4.13 93.98,74.93 96.52,77.47 96.52,80.01 IC4.1 | IC4.10 86.36,74.93 88.9,77.47 88.9,80.01 IC4.4 88.9,82.55 86.36,85.09 86.36,90.17 IC5.10 86.36,92.71 88.9,95.25 88.9,97.79 IC5.4 88.9,100.33 88.9,103.5 R10.1 | 43.18,105.41 v43.82,105.41
  Bottom 0.305: IC5.1 95.89,99.69 91.44,104.14 89.54,104.14 R10.1 88.27,104.14 84.46,104.14 82.55,106.05 64.14,106.05 63.5,105.41 v43.82,105.41 | IC4.13 93.35,73.03 92.08,71.75 88.27,71.75 87,73.03 IC4.10
N$9  (1 unrouted)
N$10  (1 unrouted)
N$11  (2 unrouted)
N$12  (via drill 0.61)
  Top 0.305: 38.1,116.84 38.1,118.11 IC3.4 | 38.1,116.84 38.1,115.57 35.56,113.03 IC3.10 | 38.1,116.84 41.91,113.03 41.91,93.98 43.18,92.71 E13.13 43.18,90.17 v43.18,86.36
  Bottom 0.305: v43.18,86.36 60.33,86.36 R9.1 | IC2.13 67.95,111.12 66.68,109.86 37.47,109.86 36.2,111.12 IC3.10 | IC3.1 45.09,120.02 43.82,121.28 40.01,121.28 38.74,120.02 IC3.4
N$13  (3 unrouted)
N$14  (via drill 0.61)
  Top 0.305: IC5.13 93.98,92.71 95.25,93.98 95.25,116.84 96.52,118.11 IC6.1 | E13.3 40.64,100.33 40.64,103.5 R11.1 40.64,104.78 v40.64,107.95 | IC6.10 86.36,113.03 88.9,115.57 88.9,118.11 IC6.4
  Bottom 0.305: v40.64,107.95 41.91,109.22 83.82,109.22 85.73,111.12 IC6.10 | IC6.1 95.89,118.75 94.62,117.47 90.81,117.47 89.54,118.75 IC6.4
N$15  (1 unrouted)
N$16  (1 unrouted)
N$17  (1 unrouted)
N$19  (1 unrouted)
N$22  (2 unrouted)
N$25  (2 unrouted)
N$26  (1 unrouted)
NO_SHIFT  (via drill 0.61)
  Top 0.305: v15.24,17.14 13.97,17.14 U$1.AE1
  Bottom 0.305: IC9.8 55.25,13.34 53.34,15.24 35.56,15.24 33.66,13.34 IC7.9 32.39,13.34 28.58,17.14 v15.24,17.14
PC2_H  (via drill 0.61)
  Top 0.305: v85.09,47.62 85.09,52.07 85.73,52.7 85.73,56.52 86.36,57.15 E9.5 | v15.24,42.55 13.97,42.55 U$1.AP1 | v26.04,121.28 26.67,120.65 26.67,107.95 27.31,107.31 27.31,92.71 26.04,91.44 v26.04,43.18
  Bottom 0.305: v85.09,47.62 81.92,44.45 33.02,44.45 31.75,43.18 v26.04,43.18 15.88,43.18 v15.24,42.55 | v26.04,121.28 33.66,121.28 34.93,120.02 IC3.5
PC2_L  (via drill 0.61)
  Top 0.305: v30.48,45.09 v33.66,48.26
  Bottom 0.305: v33.66,48.26 59.69,48.26 59.69,52.07 60.96,53.34 67.31,53.34 67.31,59.69 67.95,60.33 81.92,60.33 83.19,59.05 E9.6 | v30.48,45.09 13.97,45.09 U$1.AR2
PC3_H  (via drill 0.61)
  Top 0.305: IC6.5 86.36,118.11 85.09,116.84 85.09,53.34 83.82,52.07 E9.9 83.82,49.53 v81.92,47.62 | v16.51,47.62 16.51,40.01 13.97,40.01 U$1.AN1
  Bottom 0.305: v16.51,47.62 17.15,46.99 61.6,46.99 62.87,48.26 81.28,48.26 v81.92,47.62
PC3_L  (via drill 0.61)
  Top 0.305: v80.65,46.99 80.65,48.9 81.28,49.53 E9.8
  Bottom 0.305: v80.65,46.99 78.74,45.09 32.39,45.09 31.12,43.81 27.31,43.81 26.67,44.45 15.88,44.45 15.24,43.81 14.61,43.81 13.97,43.18 U$1.AP2
PC_ENABL
  Bottom 0.305: 31.12,117.47 32.39,118.75 IC3.6 | 31.12,117.47 13.97,117.47 U$1.BS2 | 31.12,117.47 81.92,117.47 83.19,118.75 IC6.6
SC2  (via drill 0.61)
  Top 0.305: v60.96,127 60.96,120.65 IC2.5 | v27.31,125.73 27.31,108.58 27.94,107.95 27.94,92.08 27.31,91.44 v27.31,87 | v18.42,87 13.97,82.55 U$1.BD1
  Bottom 0.305: v60.96,127 60.33,126.36 27.94,126.36 v27.31,125.73 | v18.42,87 v27.31,87
SC3  (via drill 0.61)
  Top 0.305: v78.74,102.23 73.03,107.95 73.03,120.65 65.41,128.27 20.32,128.27 19.69,127.64 17.78,127.64 17.78,113.03 13.97,109.22 U$1.BN1
  Bottom 0.305: v78.74,102.23 83.19,102.23 85.73,99.69 IC5.5
SC_ENABL  (via drill 0.61)
  Top 0.305: v62.23,106.68 59.69,109.22 59.69,116.84 58.42,118.11 IC2.6 | v83.82,106.68 83.82,100.33 IC5.6 | v28.58,90.81 v28.58,122.56
  Bottom 0.305: v62.23,106.68 v83.82,106.68 | v28.58,90.81 13.97,90.81 U$1.BF2 | v28.58,122.56 29.21,121.92 55.88,121.92 57.79,120.02 IC2.6
SHIFT_L1  (via drill 0.61)
  Top 0.305: v93.35,17.14 93.98,17.78 93.98,19.05 IC8.2
  Bottom 0.305: v93.35,17.14 83.19,17.14 76.84,10.79 67.95,10.79 66.68,12.06 IC9.12 | U$1.AF2 13.97,20.95 14.61,21.59 21.59,21.59 22.86,22.86 91.44,22.86 93.35,20.95 IC8.2
SHIFT_L2  (via drill 0.61)
  Top 0.305: v80.65,38.1 83.82,34.92 83.82,21.59 IC8.6 | v17.15,38.1 17.15,24.13 13.97,24.13 U$1.AH1
  Bottom 0.305: 60.96,38.1 59.06,40.01 IC10.6 | 60.96,38.1 v80.65,38.1 | v17.15,38.1 60.96,38.1
SHIFT_R1  (via drill 0.61)
  Top 0.305: v35.56,10.16 36.83,11.43 | 36.83,11.43 37.47,12.06 IC7.11 | v68.58,36.83 68.58,39.37 IC10.2 | v37.47,35.56 36.83,34.92 36.83,11.43
  Bottom 0.305: v35.56,10.16 34.93,10.79 23.5,10.79 21.59,12.7 13.97,12.7 U$1.AD2 | v68.58,36.83 67.31,35.56 v37.47,35.56
SHIFT_R2  (via drill 0.61)
  Top 0.305: v18.42,18.41 13.97,13.97 U$1.AD1
  Bottom 0.305: IC9.5 60.33,20.95 59.06,22.23 37.47,22.23 36.2,20.95 IC7.5 34.93,19.68 33.66,18.41 v18.42,18.41
SR2  (via drill 0.61)
  Top 0.305: v68.58,122.56 68.58,120.65 IC2.2 | v38.74,123.19 36.83,125.09 31.75,125.09 v31.75,89.53 | v15.24,88.27 13.97,87 U$1.BE1
  Bottom 0.305: v68.58,122.56 67.95,123.19 v38.74,123.19 | v31.75,89.53 30.48,88.27 v15.24,88.27
SR3  (via drill 0.61)
  Top 0.305: v23.5,76.2 21.59,78.11 v21.59,81.92
  Bottom 0.305: v23.5,76.2 24.13,76.83 100.33,76.83 100.33,91.44 93.98,97.79 IC5.2 | v21.59,81.92 20.96,82.55 13.97,82.55 U$1.BD2
SR_ENABL  (via drill 0.61)
  Top 0.305: v71.12,104.14 64.77,110.49 64.77,113.03 65.41,113.67 65.41,117.47 66.04,118.11 IC2.3 | v18.42,76.83 18.42,80.64 13.97,80.64 U$1.BC1 | v86.36,71.12 87.63,72.39 87.63,74.93 90.17,77.47 90.17,96.52 91.44,97.79 IC5.3
  Bottom 0.305: v71.12,104.14 71.76,103.5 87,103.5 90.81,99.69 IC5.3 | v18.42,76.83 24.13,71.12 v86.36,71.12
TT_SHIFT
  Top 0.305: R4.1 60.96,28.57 58.42,31.11 58.42,31.75 IC10.9
  Bottom 0.305: 92.08,10.79 85.73,10.79 84.46,12.06 IC8.9 | 92.08,10.79 93.35,12.06 IC8.13 | 92.08,10.79 97.79,10.79 97.79,21.59 92.71,26.67 62.87,26.67 61.6,27.94 R4.1
TT_SHIFT\
  Top 0.305: R3.1 91.44,8.26 91.44,11.43 IC8.12
  Bottom 0.305: R3.1 90.81,7.62 13.97,7.62 U$1.AB2
VCC  (via drill 0.61)  (5 unrouted)
  Top 0.305: C4.+ 22.23,106.05 20.32,104.14 20.32,71.12 22.23,69.22 C3.+ 22.86,67.94 22.86,63.5 20.96,61.59 20.96,42.55 22.23,41.27 C2.+ 23.5,40.01 24.77,38.73 24.77,6.99 23.5,5.71 C1.+ | E4.10 35.56,34.29 36.2,34.92 36.2,37.47 38.1,39.37 E4.4 | IC7.14 45.72,13.97 46.99,15.24 46.99,30.48 45.72,31.75 E4.14 45.72,34.29 45.72,39.37 E4.1 45.72,41.91 45.72,49.53 E7.14 45.72,52.07 46.99,53.34 46.99,71.12 45.72,72.39 E10.14 | 36.83,78.74 38.1,80.01 E10.4 | 36.83,78.74 36.2,78.11 36.2,75.56 35.56,74.93 E10.10 35.56,72.39 35.56,70.48 v34.29,69.22 | 36.83,78.74 36.83,96.52 38.1,97.79 E13.4 | 50.8,111.12 50.8,123.83 R8.2 | 50.8,111.12 50.8,104.78 R11.2 | E10.13 43.82,73.03 45.09,73.03 E10.14 | E10.14 45.72,74.93 45.72,80.01 E10.1 45.72,82.55 44.45,83.82 44.45,100.33 45.09,100.97 45.09,109.86 45.72,110.49 IC3.14 | v48.9,111.12 50.8,111.12 | IC9.14 71.12,13.97 72.39,15.24 72.39,23.5 71.12,24.77 R13.2 71.12,26.04 71.12,27.3 R4.2 71.12,28.57 71.12,31.75 IC10.14 71.12,34.29 69.85,35.56 69.85,50.16 | IC2.14 71.12,110.49 72.39,109.22 72.39,93.98 71.12,92.71 IC1.14 71.12,90.17 71.12,87 R9.2 71.12,85.72 72.39,84.45 72.39,76.2 71.12,74.93 E11.14 71.12,72.39 71.12,59.69 E8.1 71.12,57.15 71.12,52.07 E8.14 70.49,50.16 69.85,50.16 | E8.10 60.96,52.07 63.5,54.61 63.5,57.15 E8.4 | 69.85,50.16 69.22,50.16 E8.13 | 99.06,83.19 99.06,85.72 R5.2 | 99.06,83.19 99.06,77.47 96.52,74.93 IC4.14 96.52,72.39 96.52,59.69 E9.1 96.52,57.15 96.52,52.07 E9.14 | 99.06,83.19 106.05,83.19 C6.+ | IC6.14 96.52,110.49 96.52,107.31 99.06,104.78 R10.2 99.06,103.5 99.06,95.25 96.52,92.71 IC5.14
  Top 0.305: R1.2 99.06,126.36 99.06,125.09 R2.2 99.06,123.83 106.05,116.84 106.05,109.86 C5.+ | C8.+ 106.05,12.06 102.24,8.26 102.24,7.62 R3.2 100.97,7.62 97.16,11.43 97.16,12.06 IC8.14 96.52,13.97 95.25,15.24 95.25,21.59 93.35,23.5 93.35,48.9 | E9.4 88.9,57.15 88.9,54.61 86.36,52.07 E9.10 87,50.16 88.27,48.9 93.35,48.9 | 93.35,48.9 93.35,50.16 E9.13
  Bottom 0.305: C1.+ 22.23,4.45 13.97,4.45 U$1.AA2 | U$1.BA2 13.97,73.66 15.88,73.66 20.32,69.22 22.23,69.22 C3.+ 23.5,69.22 v34.29,69.22 | E4.13 43.82,32.38 45.09,32.38 E4.14 | E4.4 38.74,40.01 40.01,38.73 43.82,38.73 45.09,40.01 E4.1 | v48.9,111.12 46.36,111.12 IC3.14 | E10.10 36.2,74.3 37.47,75.56 41.28,75.56 42.55,74.3 E10.13 | R12.2 56.52,25.4 57.79,24.13 69.22,24.13 70.49,25.4 R13.2 | E8.10 61.6,50.16 62.87,48.9 66.68,48.9 67.95,50.16 E8.13 | IC5.14 96.52,90.17 96.52,87 99.06,87 R5.2 | R10.2 99.7,104.14 104.14,108.58 106.05,108.58 C5.+ | IC8.11 89.54,13.34 90.81,14.61 94.62,14.61 95.89,13.34 IC8.14 | E9.13 94.62,50.16 95.89,50.16 E9.14 | C7.+ 106.05,56.52 104.78,57.78 97.16,57.78 E9.1 | E8.14 71.76,50.16 73.03,48.9 84.46,48.9 85.73,50.16 E9.10 | E7.14 46.36,51.44 53.98,51.44 57.15,54.61 59.69,54.61 62.87,57.78 E8.4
